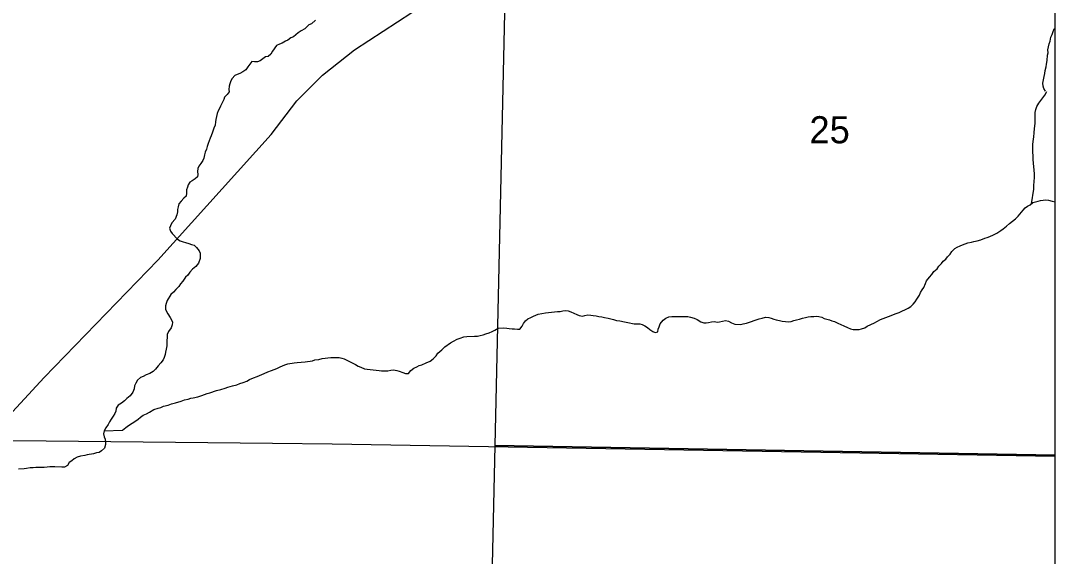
# Model space of a CAD drawing. Extents: x -10 to 158, y 8 to 33.
# Drawn here: x 29.803 to 31.4, y 19.069 to 19.897 of the extents above; entities that cross this region are included whole.
import ezdxf

# ---------------------------------------------------------------- set-up
doc = ezdxf.new("R2010")
doc.units = 0
for name, color, linetype in [('GM_X_Corporation', 7, 'Continuous'), ('GM_X_Minor_River', 7, 'Continuous'), ('GM_X_Rail_Line', 7, 'Continuous'), ('GM_X_Section_Text', 7, 'Continuous')]:
    doc.layers.add(name, color=color, linetype=linetype)

msp = doc.modelspace()

# ---------------------------------------------------------------- linework, layer by layer
at = {"layer": 'GM_X_Corporation'}
for points in [[(29.6227, 14.1), (31.4, 14.1), (31.4, 20.9), (29.731, 20.9), (29.7244, 20.2649), (29.6982, 19.2496), (29.6981, 19.2461), (29.6974, 19.2018), (29.6957, 19.0991), (29.6992, 18.9556), (29.697, 18.9465), (29.6949, 18.8465), (29.6846, 18.5133), (29.6817, 18.3306), (29.6804, 18.2238), (29.6572, 17.4131), (29.6504, 16.6563), (29.6434, 16.3848), (29.6318, 15.4937)], [(31.4, 19.2243), (31.4, 20.9), (29.731, 20.9), (29.7244, 20.2649), (29.6982, 19.2496), (29.7323, 19.249), (29.8421, 19.2479), (30.1914, 19.2443), (30.2835, 19.2432)], [(31.4, 19.2259), (31.4, 20.2429), (30.5575, 20.2545), (30.5347, 19.2405)], [(31.4, 18.3931), (31.4, 19.2259), (30.5347, 19.2405), (30.5161, 18.411)]]:
    msp.add_lwpolyline(points, close=True, dxfattribs=at)
at = {"layer": 'GM_X_Minor_River'}
for points in [[(30.258, 19.8975), (30.252, 19.892), (30.2479, 19.8901), (30.2415, 19.8843), (30.2359, 19.8811), (30.2311, 19.878), (30.224, 19.8718), (30.2198, 19.8702), (30.2154, 19.8668), (30.2116, 19.8648), (30.2067, 19.8621), (30.2026, 19.8605), (30.1977, 19.8581), (30.1918, 19.8497), (30.1889, 19.8451), (30.1848, 19.8416), (30.181, 19.8408), (30.1769, 19.8376), (30.1724, 19.8349), (30.1683, 19.8333), (30.1637, 19.8332), (30.1599, 19.8336), (30.1566, 19.8293), (30.1533, 19.8255), (30.1503, 19.8209), (30.1458, 19.8178), (30.1413, 19.815), (30.1372, 19.8138), (30.1334, 19.8119), (30.1293, 19.8076), (30.1271, 19.8038), (30.1257, 19.7992), (30.1246, 19.7954), (30.1243, 19.7905), (30.1248, 19.7867), (30.1218, 19.7828), (30.1177, 19.7786), (30.1163, 19.7748), (30.1141, 19.7698), (30.1112, 19.7648), (30.1097, 19.761), (30.1075, 19.7572), (30.1064, 19.7534), (30.1043, 19.7442), (30.1036, 19.7404), (30.103, 19.7355), (30.1012, 19.7309)], [(31.3849, 19.7876), (31.3825, 19.7917), (31.3813, 19.7955), (31.3809, 19.8004), (31.3826, 19.8107), (31.3836, 19.8153), (31.3843, 19.8195), (31.3857, 19.8252), (31.3864, 19.8297), (31.3875, 19.8354), (31.3881, 19.8434), (31.3888, 19.8472), (31.3887, 19.8518), (31.3897, 19.8563), (31.3904, 19.8609), (31.3919, 19.8651), (31.3933, 19.8712), (31.3951, 19.8754), (31.3969, 19.88), (31.3983, 19.8842), (31.4, 19.8852)], [(31.363, 19.6139), (31.3667, 19.6364), (31.367, 19.6421), (31.3676, 19.6485), (31.3679, 19.6546), (31.3678, 19.6603), (31.3673, 19.6656), (31.3668, 19.6717), (31.3664, 19.6762), (31.3659, 19.6826), (31.3658, 19.6883), (31.3653, 19.6932), (31.3651, 19.7054), (31.3658, 19.7099), (31.3665, 19.7137), (31.3668, 19.7175), (31.3675, 19.7236), (31.3681, 19.7301), (31.3684, 19.7339), (31.3687, 19.7384), (31.369, 19.7441), (31.3688, 19.7551), (31.3699, 19.7597), (31.3713, 19.7639), (31.3746, 19.7692), (31.3779, 19.7735), (31.3805, 19.7773), (31.3838, 19.7819), (31.3867, 19.7872)], [(30.1012, 19.7309), (30.099, 19.7244), (30.0968, 19.7191), (30.0954, 19.7153), (30.0936, 19.7111), (30.0925, 19.7069), (30.0907, 19.7023), (30.0896, 19.6985), (30.0878, 19.6935), (30.0867, 19.6897), (30.0857, 19.6844), (30.0839, 19.6806), (30.0809, 19.676), (30.078, 19.6721), (30.0761, 19.6683), (30.0758, 19.6637), (30.0763, 19.6592), (30.076, 19.6554), (30.0723, 19.6523), (30.0678, 19.6496), (30.064, 19.6472), (30.0614, 19.6434), (30.0604, 19.6396), (30.0589, 19.6354), (30.059, 19.6305), (30.0583, 19.6259), (30.0546, 19.6224), (30.0505, 19.6182), (30.0472, 19.6136), (30.0458, 19.609), (30.0451, 19.6052), (30.0448, 19.6014), (30.0441, 19.5968), (30.0415, 19.5903), (30.0364, 19.5846), (30.0342, 19.58), (30.0327, 19.5762), (30.0339, 19.5716), (30.0366, 19.5679), (30.0447, 19.5593), (30.0489, 19.5567), (30.0535, 19.5553), (30.0573, 19.5542), (30.0623, 19.5528), (30.0668, 19.551), (30.0706, 19.5499), (30.0745, 19.5466), (30.0783, 19.5413), (30.0799, 19.5376), (30.0801, 19.5296), (30.0772, 19.522), (30.0735, 19.5173), (30.0679, 19.5127), (30.0642, 19.5081), (30.0608, 19.5039), (30.0571, 19.5008), (30.0534, 19.4946), (30.0497, 19.4904), (30.0471, 19.4862), (30.0423, 19.4815), (30.039, 19.4773), (30.0349, 19.4738), (30.029, 19.4646), (30.0272, 19.46), (30.0265, 19.4562), (30.0266, 19.4513), (30.0278, 19.4475), (30.0301, 19.4438), (30.0336, 19.4385), (30.0359, 19.4348), (30.0371, 19.431), (30.0368, 19.4272), (30.035, 19.4223), (30.031, 19.4165), (30.0291, 19.4119), (30.0288, 19.4081), (30.0285, 19.4024), (30.0287, 19.3945), (30.0276, 19.3895), (30.0266, 19.3849), (30.0259, 19.3811), (30.0245, 19.3766), (30.023, 19.3727), (30.0193, 19.3681), (30.0152, 19.3635), (30.0111, 19.3585), (30.0074, 19.3547), (30.0022, 19.3519), (29.9965, 19.3495), (29.9917, 19.3472), (29.9879, 19.3456), (29.9831, 19.3413), (29.9805, 19.3367), (29.9787, 19.3329), (29.978, 19.3283), (29.9762, 19.323), (29.9718, 19.3172), (29.9669, 19.3134), (29.9632, 19.3095), (29.9583, 19.306), (29.9535, 19.3029)], [(30.9835, 19.4321), (30.9877, 19.4318), (30.9922, 19.4322), (30.9964, 19.4334), (31.0005, 19.4346), (31.005, 19.4359), (31.0095, 19.4375), (31.0144, 19.4383), (31.0186, 19.4391), (31.0224, 19.4396), (31.0273, 19.44), (31.0311, 19.4401), (31.0352, 19.4398), (31.0394, 19.4387), (31.0432, 19.4369), (31.0474, 19.4355), (31.0512, 19.4348), (31.055, 19.4333), (31.0592, 19.4319), (31.0642, 19.4297), (31.0733, 19.4253), (31.079, 19.4228), (31.0836, 19.4209), (31.0882, 19.4199), (31.0927, 19.4196), (31.0973, 19.42), (31.101, 19.4209), (31.1059, 19.4225), (31.1097, 19.4248), (31.1209, 19.4303), (31.1247, 19.4323), (31.1303, 19.435), (31.1341, 19.4366), (31.1386, 19.4382), (31.1427, 19.4398), (31.1543, 19.4446), (31.1592, 19.4462), (31.163, 19.4481), (31.169, 19.4505), (31.1731, 19.4529), (31.1769, 19.4552), (31.1806, 19.4587), (31.1839, 19.4625), (31.1861, 19.4667), (31.1902, 19.4729), (31.192, 19.4771), (31.1946, 19.4809), (31.1968, 19.4847), (31.1997, 19.4909), (31.2012, 19.4947), (31.2056, 19.5004), (31.2093, 19.5047), (31.2123, 19.5093), (31.2175, 19.5135), (31.2201, 19.5174), (31.2245, 19.5216), (31.2271, 19.5255), (31.2308, 19.5282), (31.2338, 19.532), (31.2379, 19.5363), (31.2405, 19.5401), (31.2449, 19.5447), (31.2487, 19.5471), (31.2532, 19.5491), (31.2569, 19.5506), (31.2652, 19.5538), (31.2705, 19.5547), (31.2743, 19.5555), (31.2795, 19.5567), (31.2852, 19.5584), (31.2912, 19.5607), (31.295, 19.5619), (31.2991, 19.5635), (31.3047, 19.5659), (31.3096, 19.5683), (31.316, 19.5725), (31.3197, 19.5753), (31.3246, 19.5791), (31.3294, 19.5834), (31.3339, 19.5873), (31.3384, 19.5908), (31.3425, 19.5946), (31.3506, 19.6039), (31.3536, 19.6077), (31.3573, 19.6104), (31.3611, 19.6124), (31.3655, 19.6159), (31.3693, 19.6171), (31.3735, 19.6179), (31.3772, 19.6188), (31.3814, 19.6196), (31.3855, 19.62), (31.3897, 19.6197), (31.395, 19.6179), (31.4, 19.6171)], [(30.5033, 19.4092), (30.5079, 19.4097), (30.512, 19.4105), (30.5169, 19.4117), (30.5211, 19.413), (30.5259, 19.4146), (30.5305, 19.4165), (30.5346, 19.4189), (30.5402, 19.4216), (30.5485, 19.4225), (30.5531, 19.4219), (30.5569, 19.4215), (30.5614, 19.4209), (30.5652, 19.4206), (30.5697, 19.4203), (30.5735, 19.4203), (30.5772, 19.4249), (30.579, 19.4291), (30.582, 19.433), (30.5857, 19.4361), (30.5906, 19.4384), (30.5944, 19.4404), (30.5981, 19.442), (30.6019, 19.4432), (30.6075, 19.4444), (30.6128, 19.4457), (30.6317, 19.4475), (30.6359, 19.4476), (30.64, 19.4484), (30.6438, 19.4489), (30.648, 19.4485), (30.6521, 19.4471), (30.6613, 19.4427), (30.6651, 19.4413), (30.67, 19.4406), (30.6738, 19.4414), (30.6783, 19.4423), (30.6829, 19.442), (30.6867, 19.4416), (30.6912, 19.441), (30.6954, 19.4399), (30.7, 19.4392), (30.7041, 19.4382), (30.7098, 19.4371), (30.714, 19.4361), (30.7178, 19.4354), (30.7224, 19.4339), (30.7277, 19.4329), (30.7349, 19.4315), (30.7399, 19.4304), (30.7501, 19.4287), (30.7539, 19.4284), (30.7584, 19.4285), (30.7622, 19.4274), (30.7664, 19.4252), (30.7703, 19.4226), (30.7741, 19.4197), (30.7787, 19.4167), (30.7825, 19.4153), (30.7863, 19.4161), (30.787, 19.4203), (30.7884, 19.4241), (30.7898, 19.4287), (30.7947, 19.4341), (30.7988, 19.4375), (30.8036, 19.4395), (30.8078, 19.44), (30.8116, 19.4397), (30.8252, 19.4399), (30.829, 19.4396), (30.8328, 19.4397), (30.8366, 19.439), (30.8427, 19.4372), (30.8469, 19.4354), (30.853, 19.4317), (30.8572, 19.4298), (30.861, 19.4299), (30.8647, 19.4304), (30.8692, 19.4316), (30.8738, 19.432), (30.878, 19.4313), (30.8817, 19.4314), (30.8908, 19.4338), (30.8957, 19.4324), (30.8999, 19.4298), (30.9053, 19.428), (30.9144, 19.4274), (30.9181, 19.4283), (30.9234, 19.4295), (30.9294, 19.4315), (30.9366, 19.4343), (30.943, 19.4363), (30.9475, 19.4375), (30.9524, 19.4387), (30.9577, 19.4381), (30.9615, 19.437), (30.9653, 19.4355), (30.9691, 19.4348), (30.974, 19.4338), (30.9782, 19.4327), (30.9835, 19.4321)], [(29.9318, 19.2631), (29.9598, 19.2643), (29.965, 19.2686), (29.9692, 19.2713), (29.9751, 19.2752), (29.9789, 19.2779), (29.9841, 19.2814), (29.9879, 19.2842), (29.992, 19.2873), (29.9972, 19.2896), (30.0017, 19.292), (30.0085, 19.2963), (30.0149, 19.2983), (30.0194, 19.2995), (30.0231, 19.3015), (30.0307, 19.3031), (30.0359, 19.3047), (30.0419, 19.3067), (30.0506, 19.3091), (30.0559, 19.3111), (30.0615, 19.3124), (30.0653, 19.3136), (30.0691, 19.314), (30.0762, 19.316), (30.0826, 19.3177), (30.0868, 19.3193), (30.0905, 19.3208), (30.0947, 19.3221), (30.1052, 19.3253), (30.112, 19.3269), (30.1184, 19.3293), (30.1229, 19.3305), (30.13, 19.3325), (30.1364, 19.3345), (30.1413, 19.3361), (30.1462, 19.3381), (30.1519, 19.3401), (30.156, 19.3425), (30.1624, 19.3449), (30.168, 19.3472), (30.1785, 19.352), (30.1842, 19.3543), (30.1902, 19.3563), (30.1943, 19.3579), (30.1981, 19.3595), (30.2033, 19.3623), (30.2108, 19.3654), (30.2154, 19.3666), (30.2252, 19.3683), (30.2297, 19.3688), (30.2422, 19.3698), (30.2535, 19.3715), (30.2572, 19.3727), (30.2633, 19.3735), (30.2682, 19.3748), (30.2731, 19.3756), (30.2769, 19.3761), (30.2814, 19.3765), (30.2905, 19.3767), (30.2943, 19.3764), (30.2984, 19.3757), (30.3022, 19.3746), (30.3114, 19.3698), (30.3156, 19.368), (30.3198, 19.3658), (30.324, 19.3632), (30.3282, 19.3614), (30.3335, 19.3592), (30.3377, 19.3585), (30.3423, 19.3579), (30.3468, 19.3576), (30.3514, 19.3569), (30.3563, 19.3562), (30.3601, 19.3559), (30.3695, 19.3561), (30.3741, 19.3569), (30.3786, 19.3574), (30.3835, 19.3563), (30.3873, 19.3552), (30.3927, 19.3531), (30.3969, 19.3516), (30.4014, 19.3517), (30.4051, 19.3563), (30.4096, 19.3598), (30.4145, 19.3622), (30.4182, 19.3641), (30.422, 19.3653), (30.4287, 19.3681), (30.4348, 19.3709), (30.4396, 19.3744), (30.4441, 19.379), (30.447, 19.3832), (30.453, 19.3886), (30.4578, 19.3929), (30.4664, 19.3991), (30.4709, 19.4015), (30.4765, 19.4046), (30.4814, 19.4062), (30.4871, 19.4082), (30.4916, 19.409), (30.5033, 19.4092)], [(29.9535, 19.3029), (29.9501, 19.2983), (29.9498, 19.2937), (29.9484, 19.2899), (29.9454, 19.2861), (29.9425, 19.2815), (29.9399, 19.2772), (29.9377, 19.273), (29.9344, 19.2677), (29.9318, 19.2631), (29.9308, 19.2585), (29.9316, 19.254), (29.9332, 19.2502), (29.9336, 19.246), (29.9337, 19.2422), (29.9323, 19.2365), (29.9278, 19.2323), (29.9241, 19.2299), (29.9199, 19.2291), (29.9154, 19.2279), (29.9056, 19.2262), (29.9018, 19.2254), (29.8951, 19.2241), (29.8902, 19.2225), (29.8853, 19.2202), (29.8816, 19.2171), (29.8778, 19.2143), (29.8749, 19.2097), (29.8704, 19.207), (29.8666, 19.2069), (29.8556, 19.2075), (29.8477, 19.2074), (29.8439, 19.2069), (29.839, 19.2068), (29.8344, 19.2064), (29.8303, 19.2067), (29.8261, 19.2066), (29.8223, 19.2062), (29.8174, 19.2061), (29.8121, 19.2052), (29.8084, 19.2048), (29.7997, 19.2039)]]:
    msp.add_lwpolyline(points, dxfattribs=at)
at = {"layer": 'GM_X_Rail_Line'}
msp.add_lwpolyline([(29.7046, 19.1813), (29.7117, 19.192), (29.7654, 19.2665), (29.8391, 19.3457), (30.0147, 19.5266), (30.1895, 19.721), (30.2294, 19.7728), (30.2689, 19.8127), (30.3183, 19.8516), (30.4952, 19.9677), (30.5837, 20.0188), (30.6456, 20.052), (30.7052, 20.0793), (30.7725, 20.1064), (30.8497, 20.1334), (30.9311, 20.1593), (30.9935, 20.1862), (31.0484, 20.213), (31.0896, 20.2587), (31.1329, 20.3362), (31.1693, 20.3714), (31.238, 20.4178), (31.3694, 20.483), (31.4, 20.5032)], dxfattribs=at)

# ---------------------------------------------------------------- texts
at = {"layer": 'GM_X_Section_Text'}
msp.add_text('25', height=0.04186, rotation=0, dxfattribs=at).set_placement((31.0205, 19.7073))

doc.saveas('drawing.dxf')
